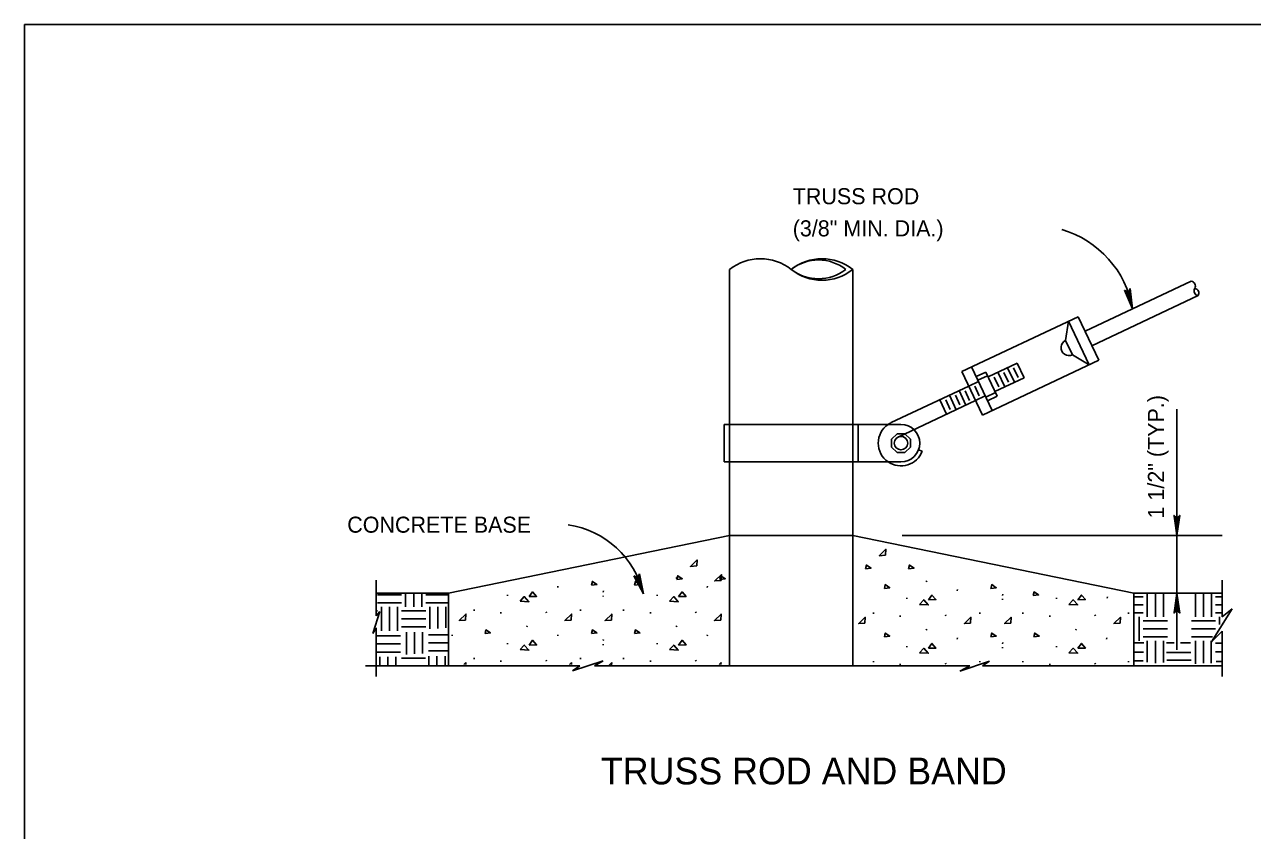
# Model space of a CAD drawing. Extents: x -123486 to -116575, y -107066 to -101122.
# Drawn here: x -119542.4 to -119083.8, y -101423.4 to -101122.4 of the extents above; entities that cross this region are included whole.
import ezdxf

# ---------------------------------------------------------------- set-up
doc = ezdxf.new("R2010")
doc.units = 0
doc.layers.add('Default', color=7, linetype='Continuous')
doc.layers.add('G-MARK', color=7, linetype='Continuous')

msp = doc.modelspace()

# ---------------------------------------------------------------- linework, layer by layer
at = {"layer": 'Default'}
msp.add_lwpolyline([(-119542.38, -101122.36), (-117742.38, -101122.36), (-117742.38, -102572.36), (-119542.38, -102572.36)], close=True, dxfattribs=at)
at = {"layer": 'G-MARK'}
for p, q in [((-119279.09, -101213.84), (-119279.09, -101271.71)), ((-119233.09, -101213.84), (-119233.09, -101271.71)), ((-119146.37, -101236.9), (-119106.69, -101218.18)), ((-119143.81, -101242.32), (-119104.13, -101223.61)), ((-119128.59, -101228.51), (-119131.61, -101221.56)), ((-119128.59, -101228.51), (-119131.21, -101221.87)), ((-119128.59, -101228.51), (-119130.9, -101222)), ((-119128.59, -101228.51), (-119130.62, -101222.05)), ((-119128.59, -101228.51), (-119130.44, -101221.71)), ((-119128.59, -101228.51), (-119130.36, -101222.02)), ((-119128.59, -101228.51), (-119130.16, -101221.94)), ((-119128.59, -101228.51), (-119129.94, -101221.78)), ((-119128.59, -101228.51), (-119129.73, -101221.51)), ((-119128.59, -101228.51), (-119129.51, -101220.98)), ((-119192.34, -101251.95), (-119148.93, -101231.47)), ((-119152.55, -101233.18), (-119153.61, -101240.31)), ((-119144.87, -101249.45), (-119152.55, -101233.18)), ((-119141.25, -101247.75), (-119148.93, -101231.47)), ((-119151.05, -101245.74), (-119153.61, -101240.31)), ((-119144.87, -101249.45), (-119151.05, -101245.74)), ((-119184.66, -101268.22), (-119192.34, -101251.95)), ((-119181.05, -101266.52), (-119188.72, -101250.24)), ((-119184.66, -101268.22), (-119141.25, -101247.75)), ((-119182.55, -101253.96), (-119171.69, -101248.84)), ((-119172.75, -101255.97), (-119175.31, -101250.55)), ((-119171.37, -101254.21), (-119173.07, -101250.6)), ((-119171.69, -101248.84), (-119169.13, -101254.27)), ((-119189.78, -101257.37), (-119186.16, -101255.67)), ((-119187.02, -101253.86), (-119183.4, -101252.15)), ((-119186.38, -101255.21), (-119182.76, -101253.51)), ((-119179.14, -101261.19), (-119183.4, -101252.15)), ((-119178.6, -101257.63), (-119180.31, -101254.01)), ((-119179.99, -101259.39), (-119169.13, -101254.27)), ((-119176.37, -101257.68), (-119178.93, -101252.25)), ((-119174.99, -101255.92), (-119176.69, -101252.3)), ((-119218.73, -101271.02), (-119189.78, -101257.37)), ((-119194.46, -101266.21), (-119197.02, -101260.78)), ((-119193.08, -101264.45), (-119194.78, -101260.83)), ((-119190.84, -101264.5), (-119193.4, -101259.07)), ((-119189.46, -101262.74), (-119191.16, -101259.13)), ((-119185.84, -101261.04), (-119187.55, -101257.42)), ((-119187.22, -101262.8), (-119183.61, -101261.09)), ((-119183.39, -101261.54), (-119179.78, -101259.84)), ((-119216.17, -101276.45), (-119187.22, -101262.8)), ((-119198.08, -101267.91), (-119200.64, -101262.49)), ((-119196.69, -101266.16), (-119198.4, -101262.54)), ((-119182.75, -101262.9), (-119179.14, -101261.19)), ((-119112.05, -101313.18), (-119112.05, -101265.97)), ((-119281.09, -101271.71), (-119215.09, -101271.71)), ((-119281.09, -101271.71), (-119281.09, -101285.71)), ((-119279.09, -101271.71), (-119279.09, -101285.71)), ((-119233.09, -101271.71), (-119233.09, -101285.71)), ((-119231.09, -101271.71), (-119231.09, -101285.71)), ((-119218.59, -101277.26), (-119216.54, -101275.21)), ((-119218.59, -101280.16), (-119218.59, -101277.26)), ((-119216.54, -101275.21), (-119213.64, -101275.21)), ((-119213.64, -101275.21), (-119211.59, -101277.26)), ((-119211.59, -101280.16), (-119211.59, -101277.26)), ((-119218.59, -101280.16), (-119216.54, -101282.21)), ((-119216.54, -101282.21), (-119213.64, -101282.21)), ((-119213.64, -101282.21), (-119211.59, -101280.16)), ((-119208.55, -101281.2), (-119207.15, -101281.74)), ((-119281.09, -101285.71), (-119215.09, -101285.71)), ((-119279.09, -101285.71), (-119279.09, -101361.84)), ((-119233.09, -101285.71), (-119233.09, -101361.84)), ((-119279.09, -101313.18), (-119384.09, -101334.71)), ((-119279.09, -101313.18), (-119233.09, -101313.18)), ((-119233.09, -101313.18), (-119128.09, -101334.71)), ((-119095.12, -101313.18), (-119214.69, -101313.18)), ((-119112.05, -101334.71), (-119112.05, -101313.18)), ((-119411.12, -101329.84), (-119411.12, -101343.18)), ((-119311.24, -101334.95), (-119314.82, -101328.27)), ((-119311.24, -101334.95), (-119314.4, -101328.55)), ((-119311.24, -101334.95), (-119314.08, -101328.65)), ((-119311.24, -101334.95), (-119313.8, -101328.68)), ((-119311.24, -101334.95), (-119313.54, -101328.63)), ((-119311.24, -101334.95), (-119313.35, -101328.54)), ((-119311.24, -101334.95), (-119313.14, -101328.35)), ((-119311.24, -101334.95), (-119312.95, -101328.07)), ((-119311.24, -101334.95), (-119312.78, -101327.53)), ((-119299, -101329.29), (-119298.82, -101328.9)), ((-119095.12, -101329.84), (-119095.12, -101343.58)), ((-119343.26, -101332.65), (-119343.19, -101332.17)), ((-119326.3, -101334.4), (-119326.23, -101333.91)), ((-119287.45, -101332.65), (-119287.38, -101332.17)), ((-119205.69, -101330.47), (-119205.5, -101330.08)), ((-119194.13, -101333.83), (-119194.05, -101333.35)), ((-119411.12, -101334.71), (-119384.09, -101334.71)), ((-119410.58, -101335.33), (-119401.58, -101335.33)), ((-119410.58, -101338.33), (-119401.58, -101338.33)), ((-119384.09, -101334.71), (-119384.09, -101361.84)), ((-119362.03, -101335.69), (-119361.98, -101335.33)), ((-119326.34, -101336.04), (-119326.3, -101335.68)), ((-119306.2, -101335.69), (-119306.16, -101335.33)), ((-119212.89, -101336.87), (-119212.85, -101336.51)), ((-119177.21, -101337.22), (-119177.16, -101336.86)), ((-119177.16, -101335.58), (-119177.09, -101335.09)), ((-119157.06, -101336.87), (-119157.02, -101336.51)), ((-119138.07, -101336.65), (-119138, -101336.17)), ((-119128.09, -101334.71), (-119128.09, -101361.84)), ((-119128.09, -101334.71), (-119095.12, -101334.71)), ((-119112.05, -101355.9), (-119112.05, -101334.71)), ((-119409.71, -101341.54), (-119412.37, -101349.8)), ((-119411.12, -101343.18), (-119409.71, -101341.54)), ((-119409.08, -101348.84), (-119409.08, -101339.84)), ((-119406.08, -101348.84), (-119406.08, -101339.84)), ((-119401.58, -101341.34), (-119392.57, -101341.34)), ((-119374.51, -101341.29), (-119374.51, -101340.84)), ((-119364.5, -101342.37), (-119364.5, -101341.88)), ((-119347.46, -101342.03), (-119347.6, -101341.67)), ((-119334.76, -101341.29), (-119334.76, -101340.84)), ((-119318.7, -101341.29), (-119318.7, -101340.84)), ((-119308.68, -101342.37), (-119308.68, -101341.88)), ((-119291.64, -101342.03), (-119291.79, -101341.67)), ((-119225.37, -101342.47), (-119225.37, -101342.02)), ((-119215.37, -101343.55), (-119215.37, -101343.06)), ((-119198.33, -101343.21), (-119198.46, -101342.85)), ((-119185.62, -101342.47), (-119185.62, -101342.02)), ((-119169.56, -101342.47), (-119169.56, -101342.02)), ((-119159.54, -101343.55), (-119159.54, -101343.06)), ((-119142.5, -101343.21), (-119142.65, -101342.85)), ((-119130.08, -101342.47), (-119130.08, -101342.02)), ((-119126.1, -101352.6), (-119126.1, -101343.6)), ((-119091.41, -101340.64), (-119099.14, -101352.9)), ((-119095.12, -101343.58), (-119091.41, -101340.64)), ((-119412.37, -101349.8), (-119411.12, -101347.71)), ((-119411.12, -101347.71), (-119411.12, -101365.84)), ((-119401.58, -101344.34), (-119392.57, -101344.34)), ((-119401.58, -101347.34), (-119392.57, -101347.34)), ((-119354.83, -101347.37), (-119354.63, -101346.98)), ((-119299, -101347.37), (-119298.82, -101346.98)), ((-119205.69, -101348.55), (-119205.5, -101348.16)), ((-119149.86, -101348.55), (-119149.68, -101348.16)), ((-119124.6, -101345.1), (-119115.6, -101345.1)), ((-119124.6, -101348.1), (-119115.6, -101348.1)), ((-119106.6, -101345.1), (-119097.59, -101345.1)), ((-119106.6, -101348.1), (-119097.59, -101348.1)), ((-119411, -101350.72), (-119401.99, -101350.72)), ((-119391.53, -101350.29), (-119384.09, -101350.29)), ((-119382.74, -101350.73), (-119382.67, -101350.25)), ((-119343.26, -101350.73), (-119343.19, -101350.25)), ((-119326.3, -101352.48), (-119326.23, -101351.99)), ((-119287.45, -101350.73), (-119287.38, -101350.25)), ((-119194.13, -101351.91), (-119194.05, -101351.43)), ((-119138.31, -101351.91), (-119138.24, -101351.43)), ((-119124.6, -101351.1), (-119115.6, -101351.1)), ((-119099.14, -101352.9), (-119095.12, -101348.91)), ((-119095.12, -101348.91), (-119095.12, -101365.84)), ((-119411, -101353.72), (-119401.99, -101353.72)), ((-119411, -101356.72), (-119401.99, -101356.72)), ((-119391.53, -101353.29), (-119384.09, -101353.29)), ((-119391.53, -101356.29), (-119384.09, -101356.29)), ((-119362.03, -101353.77), (-119361.98, -101353.41)), ((-119326.34, -101354.12), (-119326.3, -101353.76)), ((-119306.2, -101353.77), (-119306.16, -101353.41)), ((-119212.89, -101354.95), (-119212.85, -101354.59)), ((-119177.21, -101355.3), (-119177.16, -101354.94)), ((-119177.16, -101353.66), (-119177.09, -101353.17)), ((-119157.06, -101354.95), (-119157.02, -101354.59)), ((-119128.09, -101353.25), (-119124.4, -101353.25)), ((-119128.09, -101356.81), (-119124.55, -101356.81)), ((-119116, -101353.35), (-119113.07, -101353.35)), ((-119115.9, -101356.86), (-119106.89, -101356.86)), ((-119110.72, -101353.35), (-119106.99, -101353.35)), ((-119097.69, -101353.4), (-119095.12, -101353.4)), ((-119097.59, -101356.61), (-119095.12, -101356.61)), ((-119415.12, -101361.84), (-119384.09, -101361.84)), ((-119401.67, -101359), (-119392.67, -101359)), ((-119384.09, -101361.84), (-119334.96, -101361.84)), ((-119374.51, -101359.37), (-119374.51, -101358.92)), ((-119364.5, -101360.45), (-119364.5, -101359.95)), ((-119347.46, -101360.1), (-119347.6, -101359.74)), ((-119326.3, -101359.99), (-119337.76, -101363.72)), ((-119337.76, -101363.72), (-119334.96, -101361.84)), ((-119334.76, -101359.37), (-119334.76, -101358.92)), ((-119329.5, -101361.84), (-119326.3, -101359.99)), ((-119329.5, -101361.84), (-119189.33, -101361.84)), ((-119318.7, -101359.37), (-119318.7, -101358.92)), ((-119308.68, -101360.45), (-119308.68, -101359.95)), ((-119291.64, -101360.1), (-119291.79, -101359.74)), ((-119225.37, -101360.55), (-119225.37, -101360.1)), ((-119215.37, -101361.63), (-119215.37, -101361.14)), ((-119198.33, -101361.29), (-119198.46, -101360.93)), ((-119182.01, -101360.19), (-119193.07, -101363.92)), ((-119193.07, -101363.92), (-119189.33, -101361.84)), ((-119185.62, -101360.55), (-119185.62, -101360.1)), ((-119184.67, -101361.84), (-119182.01, -101360.19)), ((-119184.67, -101361.84), (-119128.09, -101361.84)), ((-119169.56, -101360.55), (-119169.56, -101360.1)), ((-119159.54, -101361.63), (-119159.54, -101361.14)), ((-119142.5, -101361.29), (-119142.65, -101360.93)), ((-119130.08, -101360.55), (-119130.08, -101360.1)), ((-119128.09, -101360.01), (-119124.6, -101360.01)), ((-119128.09, -101361.84), (-119095.12, -101361.84)), ((-119115.8, -101359.76), (-119106.79, -101359.76)), ((-119097.39, -101360.26), (-119095.12, -101360.26))]:
    msp.add_line(p, q, dxfattribs=at)
for points in [[(-119129.51, -101220.98), (-119129.73, -101221.51), (-119129.94, -101221.78), (-119130.16, -101221.94), (-119130.39, -101222.02), (-119130.62, -101222.05), (-119130.9, -101222), (-119131.21, -101221.87), (-119131.61, -101221.56)], [(-119110.97, -101305.67), (-119112.05, -101313.18), (-119113.14, -101305.68), (-119112.96, -101305.91), (-119112.63, -101306.24), (-119112.33, -101306.4), (-119112.05, -101306.44), (-119111.73, -101306.38), (-119111.42, -101306.21), (-119111.12, -101305.87), (-119110.97, -101305.67), (-119112.04, -101312.95), (-119113.07, -101305.92), (-119112.9, -101306.13), (-119112.57, -101306.48), (-119112.15, -101306.59), (-119111.72, -101306.52), (-119111.43, -101306.31), (-119111.19, -101306.07), (-119111.06, -101305.9), (-119112.04, -101312.56), (-119112.95, -101306.23), (-119112.8, -101306.46), (-119112.62, -101306.57), (-119112.38, -101306.7), (-119112.04, -101306.76), (-119111.76, -101306.73), (-119111.55, -101306.59), (-119111.37, -101306.32), (-119111.16, -101306.14), (-119112.04, -101312.1), (-119112.81, -101306.58), (-119112.51, -101306.83), (-119112.14, -101306.9), (-119111.72, -101306.86), (-119111.27, -101306.39), (-119112.02, -101311.58), (-119112.67, -101306.9), (-119112.45, -101306.97), (-119112.11, -101307.11), (-119111.73, -101307.02), (-119111.4, -101306.65), (-119112.02, -101311.11), (-119112.53, -101307.07), (-119112.27, -101307.2), (-119111.99, -101307.26), (-119111.55, -101306.98), (-119112.02, -101310.54), (-119112.41, -101307.31), (-119112.21, -101307.4), (-119111.99, -101307.43), (-119111.67, -101307.2), (-119112.02, -101309.87), (-119112.28, -101307.52), (-119111.97, -101307.58), (-119111.79, -101307.37), (-119112.02, -101309.32), (-119112.19, -101307.67), (-119111.9, -101307.64), (-119112.02, -101308.75), (-119112.09, -101307.74), (-119112, -101307.71), (-119112, -101308.06)], [(-119312.78, -101327.53), (-119312.95, -101328.07), (-119313.14, -101328.35), (-119313.35, -101328.54), (-119313.57, -101328.63), (-119313.8, -101328.68), (-119314.08, -101328.65), (-119314.4, -101328.55), (-119314.82, -101328.27)], [(-119400.08, -101339.84), (-119400.08, -101334.95)], [(-119397.07, -101339.84), (-119397.07, -101334.94)], [(-119394.07, -101339.84), (-119394.07, -101334.93)], [(-119392.57, -101335.33), (-119384.32, -101335.33)], [(-119392.57, -101338.33), (-119384.32, -101338.33)], [(-119127.78, -101336.1), (-119124.6, -101336.1)], [(-119123.1, -101343.6), (-119123.1, -101335.06)], [(-119120.1, -101343.6), (-119120.1, -101335.04)], [(-119117.1, -101343.6), (-119117.1, -101335.03)], [(-119113.14, -101342.21), (-119112.05, -101334.71), (-119110.97, -101342.21), (-119111.15, -101341.97), (-119111.47, -101341.64), (-119111.77, -101341.48), (-119112.05, -101341.44), (-119112.37, -101341.5), (-119112.68, -101341.67), (-119112.99, -101342.01), (-119113.14, -101342.21), (-119112.06, -101334.93), (-119111.04, -101341.97), (-119111.2, -101341.75), (-119111.53, -101341.4), (-119111.96, -101341.29), (-119112.38, -101341.37), (-119112.68, -101341.57), (-119112.92, -101341.82), (-119113.05, -101341.99), (-119112.06, -101335.33), (-119111.16, -101341.65), (-119111.3, -101341.43), (-119111.49, -101341.31), (-119111.73, -101341.19), (-119112.06, -101341.12), (-119112.34, -101341.16), (-119112.56, -101341.29), (-119112.73, -101341.56), (-119112.94, -101341.74), (-119112.06, -101335.79), (-119111.29, -101341.3), (-119111.6, -101341.06), (-119111.97, -101340.98), (-119112.38, -101341.02), (-119112.83, -101341.49), (-119112.09, -101336.3), (-119111.43, -101340.98), (-119111.65, -101340.92), (-119112, -101340.77), (-119112.37, -101340.86), (-119112.7, -101341.24), (-119112.09, -101336.78), (-119111.57, -101340.82), (-119111.84, -101340.68), (-119112.12, -101340.62), (-119112.56, -101340.91), (-119112.09, -101337.34), (-119111.69, -101340.57), (-119111.89, -101340.48), (-119112.12, -101340.46), (-119112.44, -101340.68), (-119112.09, -101338.01), (-119111.82, -101340.37), (-119112.13, -101340.3), (-119112.32, -101340.52), (-119112.09, -101338.57), (-119111.91, -101340.21), (-119112.21, -101340.25), (-119112.09, -101339.13), (-119112.01, -101340.14), (-119112.1, -101340.17), (-119112.1, -101339.83)], [(-119105.1, -101343.6), (-119105.1, -101334.98)], [(-119102.09, -101343.6), (-119102.09, -101334.97)], [(-119099.09, -101343.6), (-119099.09, -101334.96)], [(-119097.59, -101336.1), (-119095.39, -101336.1)], [(-119411.04, -101341.34), (-119410.58, -101341.34)], [(-119403.08, -101348.78), (-119403.08, -101339.84)], [(-119391.07, -101348.09), (-119391.07, -101339.84)], [(-119388.07, -101347.91), (-119388.07, -101339.84)], [(-119385.07, -101347.74), (-119385.07, -101339.84)], [(-119127.78, -101339.1), (-119124.6, -101339.1)], [(-119127.78, -101342.1), (-119124.6, -101342.1)], [(-119097.59, -101339.1), (-119095.35, -101339.1)], [(-119097.59, -101342.1), (-119095.31, -101342.1)], [(-119096.09, -101346.4), (-119096.09, -101343.6)], [(-119399.73, -101357.61), (-119399.73, -101349.36)], [(-119396.73, -101357.44), (-119396.73, -101349.36)], [(-119393.73, -101357.26), (-119393.73, -101349.36)], [(-119123.1, -101360.52), (-119123.1, -101352.6)], [(-119120.1, -101360.87), (-119120.1, -101352.6)], [(-119117.1, -101360.62), (-119117.1, -101352.6)], [(-119106.6, -101351.1), (-119098.72, -101351.1)], [(-119105.1, -101361.17), (-119105.1, -101352.6)], [(-119102.09, -101360.92), (-119102.09, -101352.6)], [(-119099.24, -101360.87), (-119099.24, -101352.55)], [(-119409.73, -101361.84), (-119409.73, -101358.55)], [(-119406.73, -101361.84), (-119406.73, -101358.55)], [(-119403.73, -101361.84), (-119403.73, -101358.55)], [(-119391.36, -101361.84), (-119391.36, -101358.31)], [(-119388.36, -101361.84), (-119388.36, -101358.31)], [(-119385.36, -101361.84), (-119385.36, -101358.31)], [(-119377.57, -101360.63), (-119378.31, -101361.35)], [(-119377.61, -101361.35), (-119377.57, -101360.63)], [(-119338.1, -101360.63), (-119338.84, -101361.35)], [(-119338.14, -101361.35), (-119338.1, -101360.63)], [(-119323.11, -101360.63), (-119324.11, -101361.6)], [(-119323.16, -101361.6), (-119323.11, -101360.63)], [(-119282.28, -101360.63), (-119283.04, -101361.37)], [(-119282.32, -101361.37), (-119282.28, -101360.63)]]:
    msp.add_lwpolyline(points, dxfattribs=at)
for points in [[(-119220.87, -101320.58), (-119220.75, -101318.36), (-119223.21, -101320.76)], [(-119291.38, -101324.54), (-119291.26, -101322.32), (-119293.72, -101324.72)], [(-119228.31, -101325.67), (-119226.29, -101325.4), (-119227.98, -101324.27)], [(-119212.23, -101325.67), (-119210.22, -101325.4), (-119211.92, -101324.27)], [(-119298.81, -101329.62), (-119296.79, -101329.35), (-119298.48, -101328.23)], [(-119282.27, -101330), (-119282.15, -101327.78), (-119284.61, -101330.18)], [(-119282.74, -101329.62), (-119280.73, -101329.35), (-119282.42, -101328.23)], [(-119354, -101336.04), (-119352.67, -101334.27), (-119351.15, -101335.98)], [(-119330.66, -101331.78), (-119328.64, -101331.51), (-119330.33, -101330.38)], [(-119314.59, -101331.78), (-119312.58, -101331.51), (-119314.27, -101330.38)], [(-119298.18, -101336.04), (-119296.84, -101334.27), (-119295.33, -101335.98)], [(-119221.28, -101332.96), (-119219.27, -101332.69), (-119220.96, -101331.56)], [(-119181.53, -101332.96), (-119179.5, -101332.69), (-119181.2, -101331.56)], [(-119165.7, -101335.66), (-119163.69, -101335.39), (-119165.38, -101334.26)], [(-119357.35, -101337.75), (-119355.76, -101336.04), (-119354.06, -101337.93)], [(-119301.52, -101337.75), (-119299.95, -101336.04), (-119298.24, -101337.93)], [(-119208.21, -101338.93), (-119206.62, -101337.22), (-119204.93, -101339.11)], [(-119204.87, -101337.22), (-119203.53, -101335.45), (-119202.02, -101337.16)], [(-119152.38, -101338.93), (-119150.81, -101337.22), (-119149.1, -101339.11)], [(-119149.04, -101337.22), (-119147.7, -101335.45), (-119146.19, -101337.16)], [(-119377.69, -101344.77), (-119377.57, -101342.55), (-119380.03, -101344.95)], [(-119338.22, -101344.77), (-119338.1, -101342.55), (-119340.56, -101344.95)], [(-119323.23, -101344.77), (-119323.11, -101342.55), (-119325.57, -101344.95)], [(-119282.4, -101344.77), (-119282.28, -101342.55), (-119284.74, -101344.95)], [(-119228.55, -101345.95), (-119228.43, -101343.73), (-119230.89, -101346.13)], [(-119189.09, -101345.95), (-119188.97, -101343.73), (-119191.43, -101346.13)], [(-119174.09, -101345.95), (-119173.97, -101343.73), (-119176.43, -101346.13)], [(-119133.26, -101345.95), (-119133.14, -101343.73), (-119135.6, -101346.13)], [(-119370.41, -101349.86), (-119368.4, -101349.59), (-119370.1, -101348.46)], [(-119354, -101354.12), (-119352.67, -101352.35), (-119351.15, -101354.06)], [(-119330.66, -101349.86), (-119328.64, -101349.59), (-119330.33, -101348.46)], [(-119314.59, -101349.86), (-119312.58, -101349.59), (-119314.27, -101348.46)], [(-119298.18, -101354.12), (-119296.84, -101352.35), (-119295.33, -101354.06)], [(-119221.28, -101351.04), (-119219.27, -101350.77), (-119220.96, -101349.64)], [(-119181.53, -101351.04), (-119179.5, -101350.77), (-119181.2, -101349.64)], [(-119165.45, -101351.04), (-119163.44, -101350.77), (-119165.13, -101349.64)], [(-119357.35, -101355.83), (-119355.76, -101354.12), (-119354.06, -101356.01)], [(-119301.52, -101355.83), (-119299.95, -101354.12), (-119298.24, -101356.01)], [(-119208.21, -101357.01), (-119206.62, -101355.3), (-119204.93, -101357.19)], [(-119204.87, -101355.3), (-119203.53, -101353.53), (-119202.02, -101355.24)], [(-119152.38, -101357.01), (-119150.81, -101355.3), (-119149.1, -101357.19)], [(-119149.04, -101355.3), (-119147.7, -101353.53), (-119146.19, -101355.24)]]:
    msp.add_lwpolyline(points, close=True, dxfattribs=at)
msp.add_circle((-119215.09, -101278.71), 2.5, dxfattribs=at)
for centre, radius, start, end in [((-119165.58, -101234.98), 37.55, 9.9133, 73.7165), ((-119267.59, -101228.37), 18.53, 51.6435, 128.3565), ((-119244.59, -101228.37), 18.53, 51.642, 128.358), ((-119245.87, -101226.77), 16.48, 51.6669, 128.3331), ((-119244.59, -101199.31), 18.53, 231.642, 308.358), ((-119245.87, -101200.44), 16.86, 232.6766, 307.3234), ((-119106.96, -101219.97), 1.81, 329.1023, 81.4128), ((-119103.86, -101221.82), 1.81, 149.0911, 261.4168), ((-119105.68, -101222.68), 1.81, 329.1292, 81.3788), ((-119152.33, -101243.02), 3, 115.2499, 295.2662), ((-119215.09, -101278.71), 8.5, 124.5613, 235.4387), ((-119215.09, -101278.71), 8.5, 115.4436, 124.5536), ((-119215.09, -101278.71), 7, 270, 90), ((-119215.09, -101278.71), 8.5, 235.4387, 339.1299), ((-119344.44, -101343), 34.17, 13.6289, 81.3976)]:
    msp.add_arc(centre, radius, start, end, dxfattribs=at)

# ---------------------------------------------------------------- texts
for s, height, p in [('TRUSS ROD', 6, (-119255.52, -101189.48)), ('(3/8" MIN. DIA.)', 6, (-119255.52, -101201.48)), ('CONCRETE BASE', 6, (-119421.88, -101312.16)), ('TRUSS ROD AND BAND', 10, (-119327.17, -101406.17))]:
    msp.add_text(s, height=height, dxfattribs=at).set_placement(p)
msp.add_text('1 1/2" (TYP.)', height=6, rotation=90, dxfattribs=at).set_placement((-119116.89, -101306.85))

doc.saveas('drawing.dxf')
